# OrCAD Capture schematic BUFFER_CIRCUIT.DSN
size A
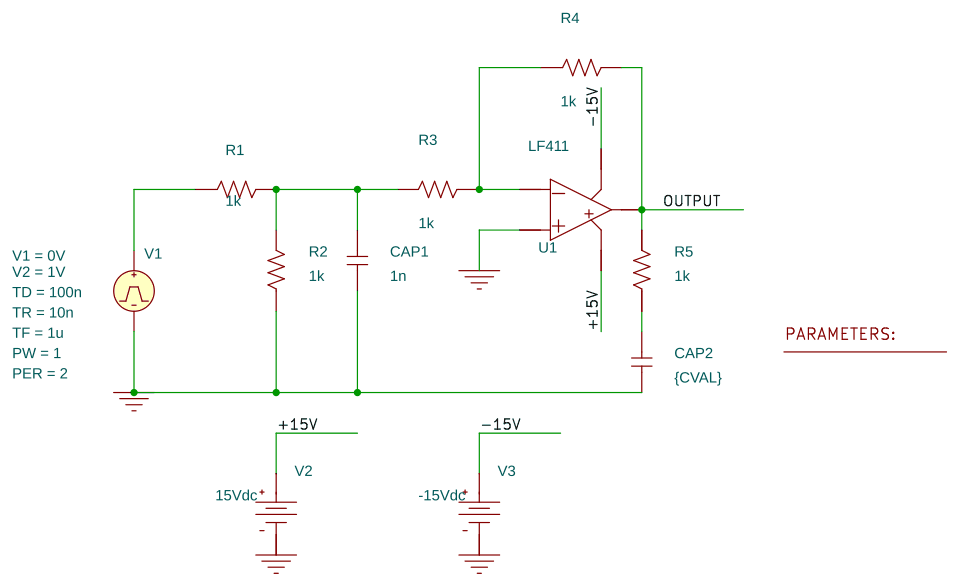
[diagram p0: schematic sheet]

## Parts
1  PARAM
CAP1  1n  [CK05]
CAP2  {CVAL}  [CK05]
R1  1k  [RC05]
R2  1k  [RC05]
R3  1k  [RC05]
R4  1k  [RC05]
R5  1k  [RC05]
U1  LF411  [DIP1008W300L450]
V1  VPULSE
V2  VDC
V3  VDC

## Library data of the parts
1 = PARAM: CVAL: 0.1n
CAP1 CAP2 = C
R1-R5 = R
U1 = LF411
V1 = VPULSE: PER: 2; PW: 1; TD: 100n; TF: 1u; TR: 10n; V1: 0V; V2: 1V
V2 = VDC: DC: 15Vdc
V3 = VDC: DC: -15Vdc

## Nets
+15V: U1.7(PVSS) V2.0(+)
-15V: U1.4(NVSS) V3.0(+)
0: CAP1.1 CAP2.1 R2.1 U1.3(PIN) V1.2(-) V2.1(-) V3.1(-)
OUTPUT: R4.2 R5.2 U1.6(OUT)
N00356: R1.1 V1.1(+)
N00363: CAP1.2 R1.2 R2.2 R3.2
N00384: R3.1 R4.1 U1.2(NIN)
N00411: CAP2.2 R5.1
